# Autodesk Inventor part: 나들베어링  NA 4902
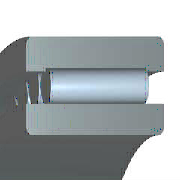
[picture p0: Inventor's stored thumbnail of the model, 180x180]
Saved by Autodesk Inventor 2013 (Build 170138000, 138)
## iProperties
Created: 2012-02
Part Number: 나들베어링  NA 4902
Material: 강철, 연강
Description: 니들 롤러 베어링
Document SubType Name: Modeling
Standard: JIS B 1536
Designer: mdu-01
Standards Organization: JIS
Language: ko-KR
Size Designation: NA 4902 15x28x13
Categories: <MemberInstance><Categories><Category DisplayName="샤프트 부품" InternalName="7f7aeb1f-a693-4053-b835-cee3144e0d98" Mnemonic="SHFT"><Category DisplayName="베어링" Inter
Density: 1 g/cm^3
IsCustomPart: 1
Author: mdu-01
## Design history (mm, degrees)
sketch "스케치"
  geometry: L1 (1.857, 11.5)-(11.143, 11.5); L2 (11.143, 11.5)-(11.143, 10); L3 (13, 10)-(0, 10); L4 (1.857, 10)-(1.857, 11.5); L5 (1.857, 10.75)-(11.143, 10.75); L6 (6.5, 10.75)-(6.5, 10); L7 (0, 7.5)-(13, 7.5); L8 (0, 14)-(13, 14); L9 (13, 7.5)-(13, 10); L10 (13, 11.35)-(13, 14); L11 (1.857, 11.35)-(0, 11.35); L12 (11.143, 11.35)-(13, 11.35); L13 (-6, 0)-(36, 0) reference; L14 (0, -1.9)-(0, 14.9) reference
  constraints: 24 end point, 8 point on line, 3 midpoint, 3 parallel, 3 perpendicular, 2 symmetric about line, 1 horizontal, 1 other
  dimensions: "d6" = 15 diameter of L7 L13 (= WD); "d7" = 20 diameter of L3 L13 (= KID1); "d8" = 28 diameter of L8 L13 (= BD); "d9" = 21.5 diameter of L6.start L13 (= 0.5 x WD + 0.5 x BD); "d10" = 22.7 diameter of L12 L13 (= 0.9 x BD + 0.9 x WD - 0.8 x KID1); "d11" = 23 diameter of L1 L13 (= BD + WD - KID1); "d12" = 1.85714 distance between parallel lines of L14 L4 (= 0.142857 x KB); "d13" = 13 distance between parallel lines of L14 L9 (= KB); "d14" = 11.14286 distance between parallel lines of L14 L2 (= 0.857143 x KB)
revolve "본체" stored, may be unused: angle "d17" = 90 deg
revolve "롤러" stored, may be unused: angle "d18" = 90 deg
body "Solid1"
fillet "모깎기1" dims "d0" = 0.3 (= KRS)
pattern_circular "IDS_ARRAYROLLER[SIMPL:T]" dims angle "d2" = 360 deg
other parameters: "WD" = 15 [user parameter; used in 6 equation terms], "BD" = 28 [user parameter; used in 6 equation terms], "KB" = 13 [user parameter; used in 3 equation terms], "KID1" = 20 [user parameter; used in 4 equation terms], "KRS" = 0.3 [user parameter; used in 1 equation term], "d3" = 0, "d4" = 0, "d5" = 0, "d15" = 0, "d16" = 0, "BC0" = 1.37e+07 [user parameter], "WR" = 7.5 (= 0.5 x WD) [user parameter], "BBA" = 0 [user parameter], "BC" = 1.02e+07 [user parameter], "BR" = 14 (= 0.5 x BD) [user parameter]
